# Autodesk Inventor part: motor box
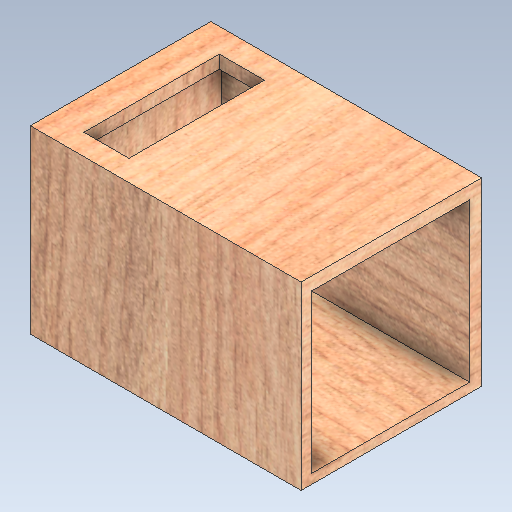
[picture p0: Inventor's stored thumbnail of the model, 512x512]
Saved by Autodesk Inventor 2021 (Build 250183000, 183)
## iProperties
Created: 2021-06
Part Number: motor box
Material: Wood (Birch)
Document SubType Name: Modeling
Designer: adams
Density: 0.55 g/cm^3
Appearance: Birch - Natural Polished
Author: adams
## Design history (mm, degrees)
sketch "Sketch1"
  geometry: L1 (-62.196, 38.924)-(90.204, 38.924); L2 (90.204, 38.924)-(90.204, -62.676); L3 (90.204, -62.676)-(-62.196, -62.676); L4 (-62.196, -62.676)-(-62.196, 38.924); 1 further point
  constraints: 8 end point, 2 parallel, 1 horizontal, 1 perpendicular
  dimensions: "d0" = 152.4 distance of L1.start L1.end; "d1" = 101.6 distance of L1.end L2.end
extrude "Extrusion1" new body sketch "Sketch1" distance "d2" = 101.6; taper "d3" = 0 deg
sketch "Sketch2"
  geometry: L1 (-95.654, 94.276)-(-6.754, 94.276); L2 (-6.754, 94.276)-(-6.754, 5.376); L3 (-6.754, 5.376)-(-95.654, 5.376); L4 (-95.654, 5.376)-(-95.654, 94.276); 1 further point
  constraints: 8 end point, 2 parallel, 1 horizontal, 1 perpendicular
  dimensions: "d4" = 88.9 distance of L1.start L1.end; "d5" = 88.9 distance of L1.end L2.end
extrude "Extrusion2" cut sketch "Sketch2" distance "d6" = 139.7; taper "d7" = 0 deg
sketch "Sketch3"
  geometry: L1 (18.273, -13.543)-(43.673, -13.543); L2 (43.673, -13.543)-(43.673, -89.743); L3 (43.673, -89.743)-(18.273, -89.743); L4 (18.273, -89.743)-(18.273, -13.543); 1 further point
  constraints: 8 end point, 2 parallel, 1 horizontal, 1 perpendicular
  dimensions: "d8" = 25.4 distance of L1.start L1.end; "d9" = 76.2 distance of L1.end L2.end
extrude "Extrusion3" cut sketch "Sketch3" distance "d10" = 12.7; taper "d11" = 0 deg
body "Solid1"
